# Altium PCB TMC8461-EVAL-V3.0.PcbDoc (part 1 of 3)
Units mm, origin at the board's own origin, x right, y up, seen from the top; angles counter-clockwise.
Board outline 79 x 85 mm, 4 copper layers (Top Layer, Mid1, Mid2, Bottom Layer), stack 1.572 mm thick; 182 components, 192 nets, 883 pads, 381 vias.
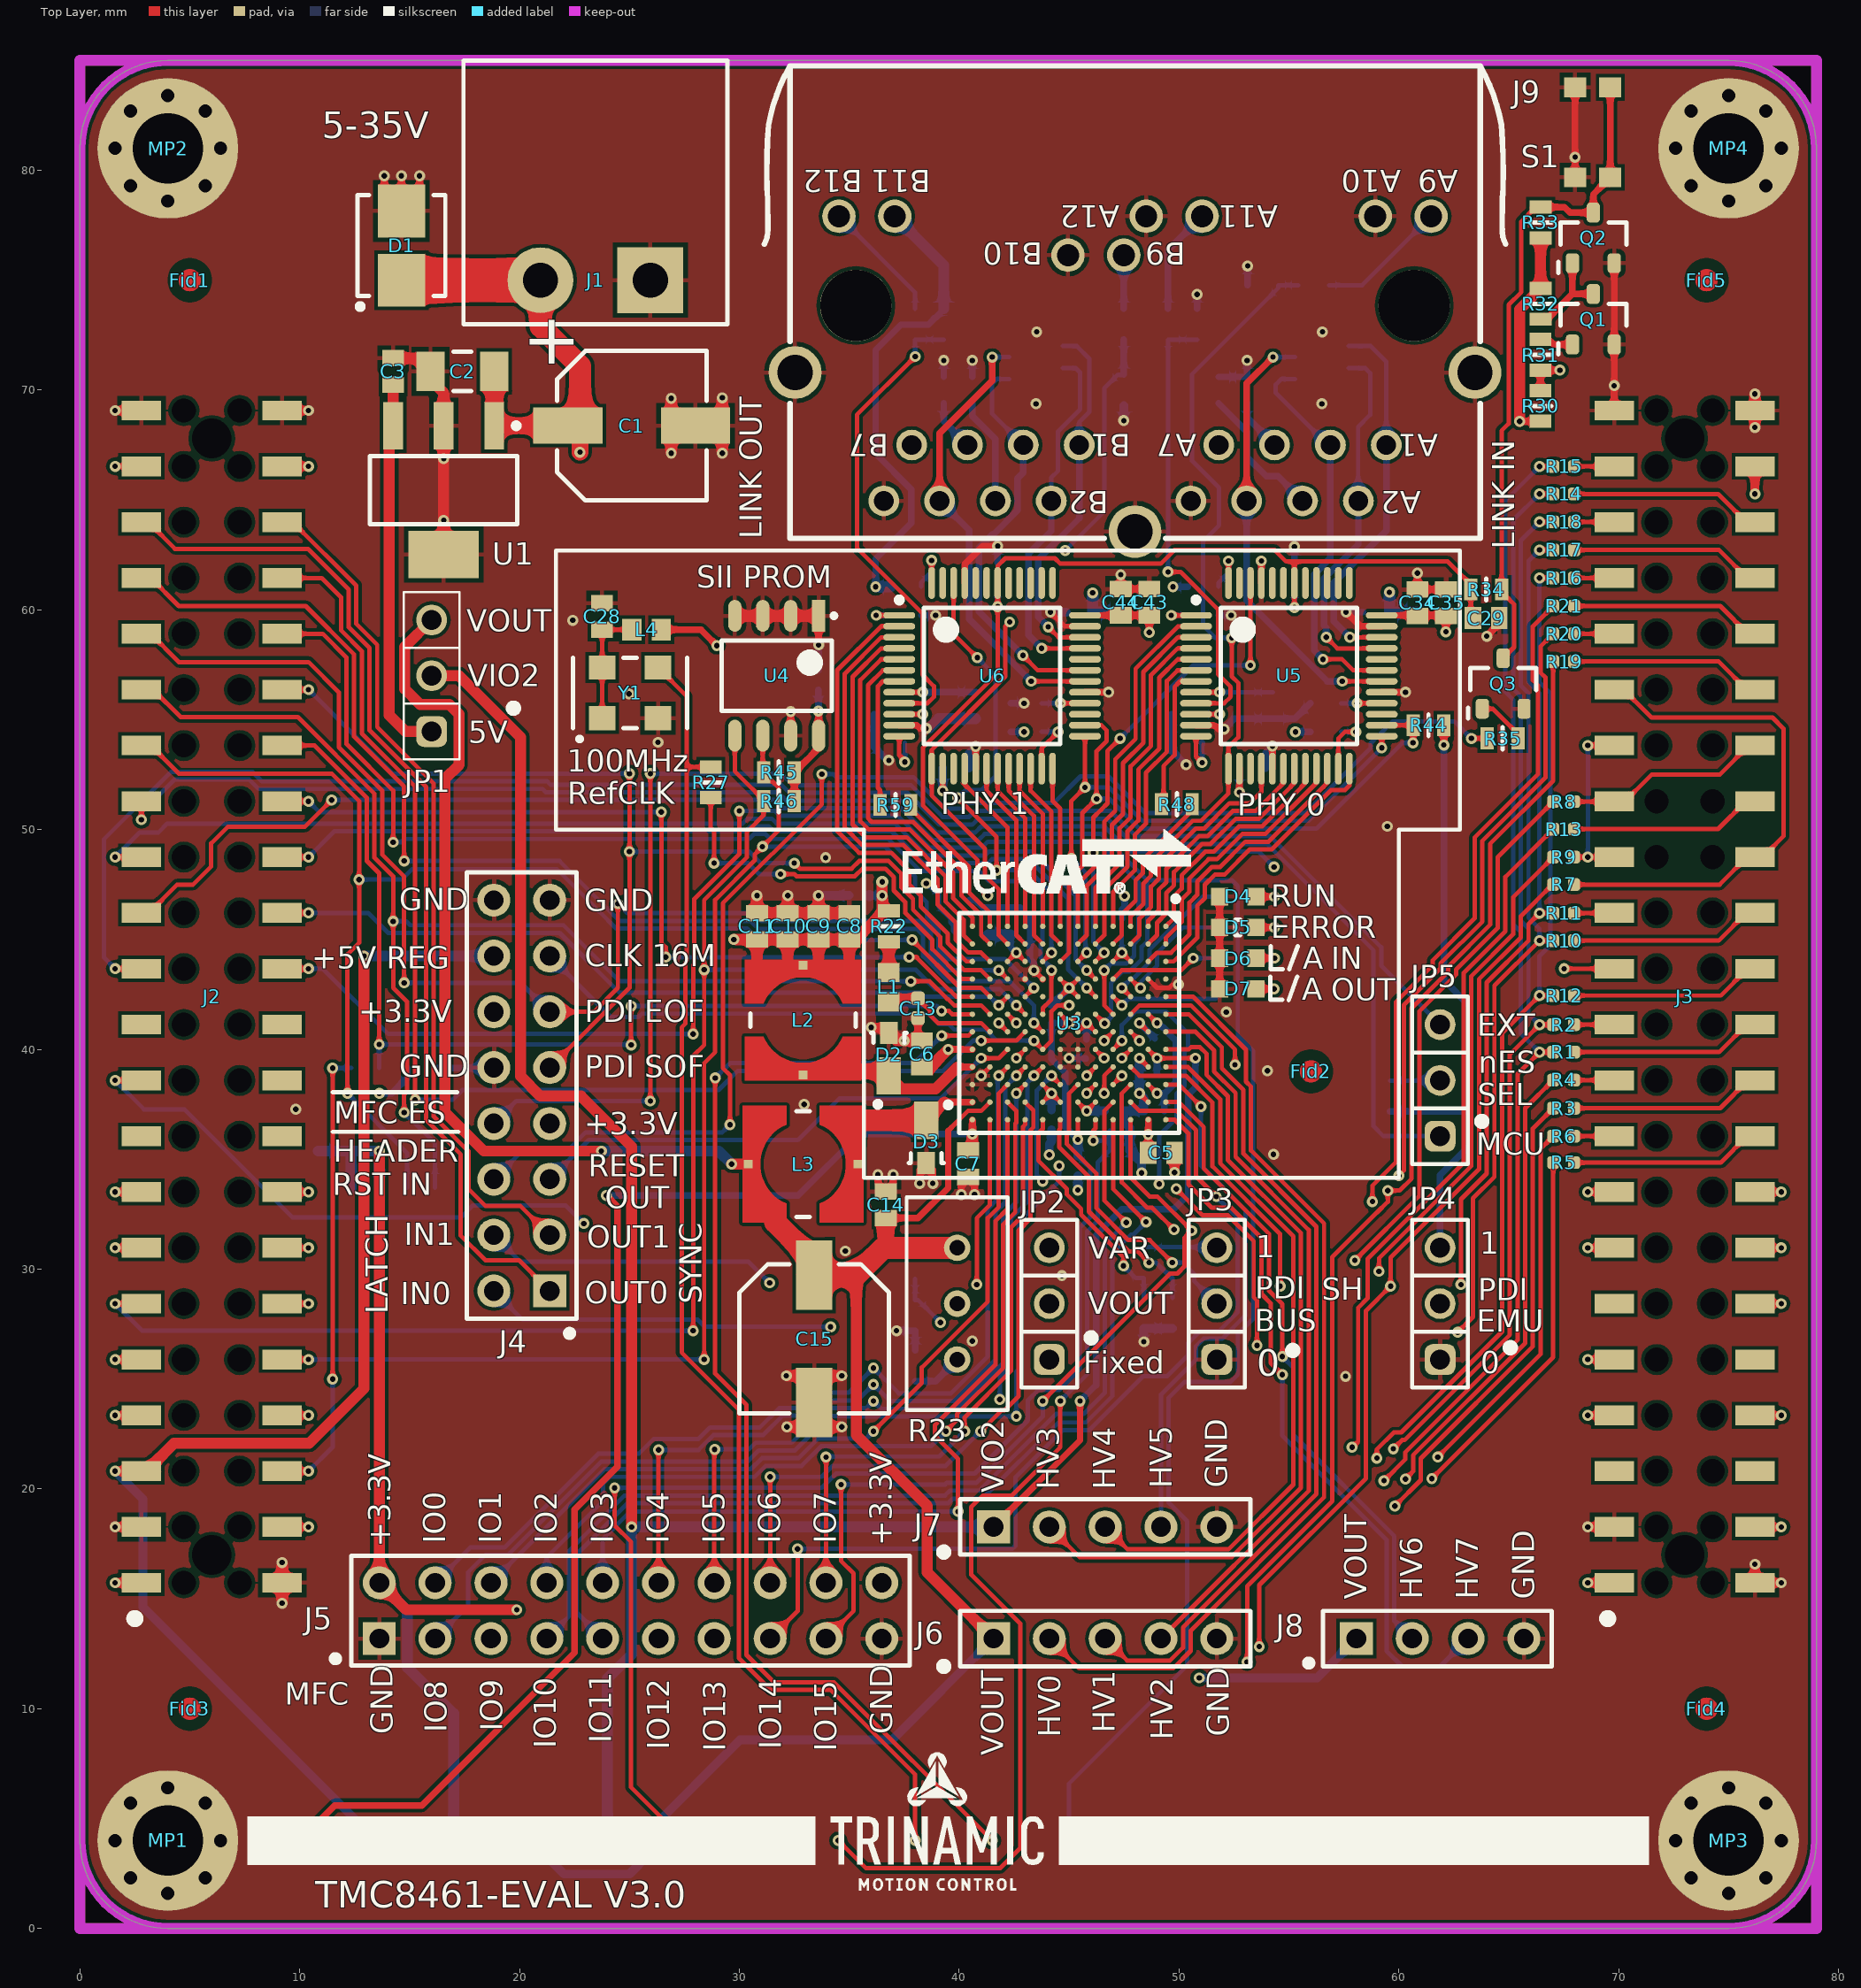
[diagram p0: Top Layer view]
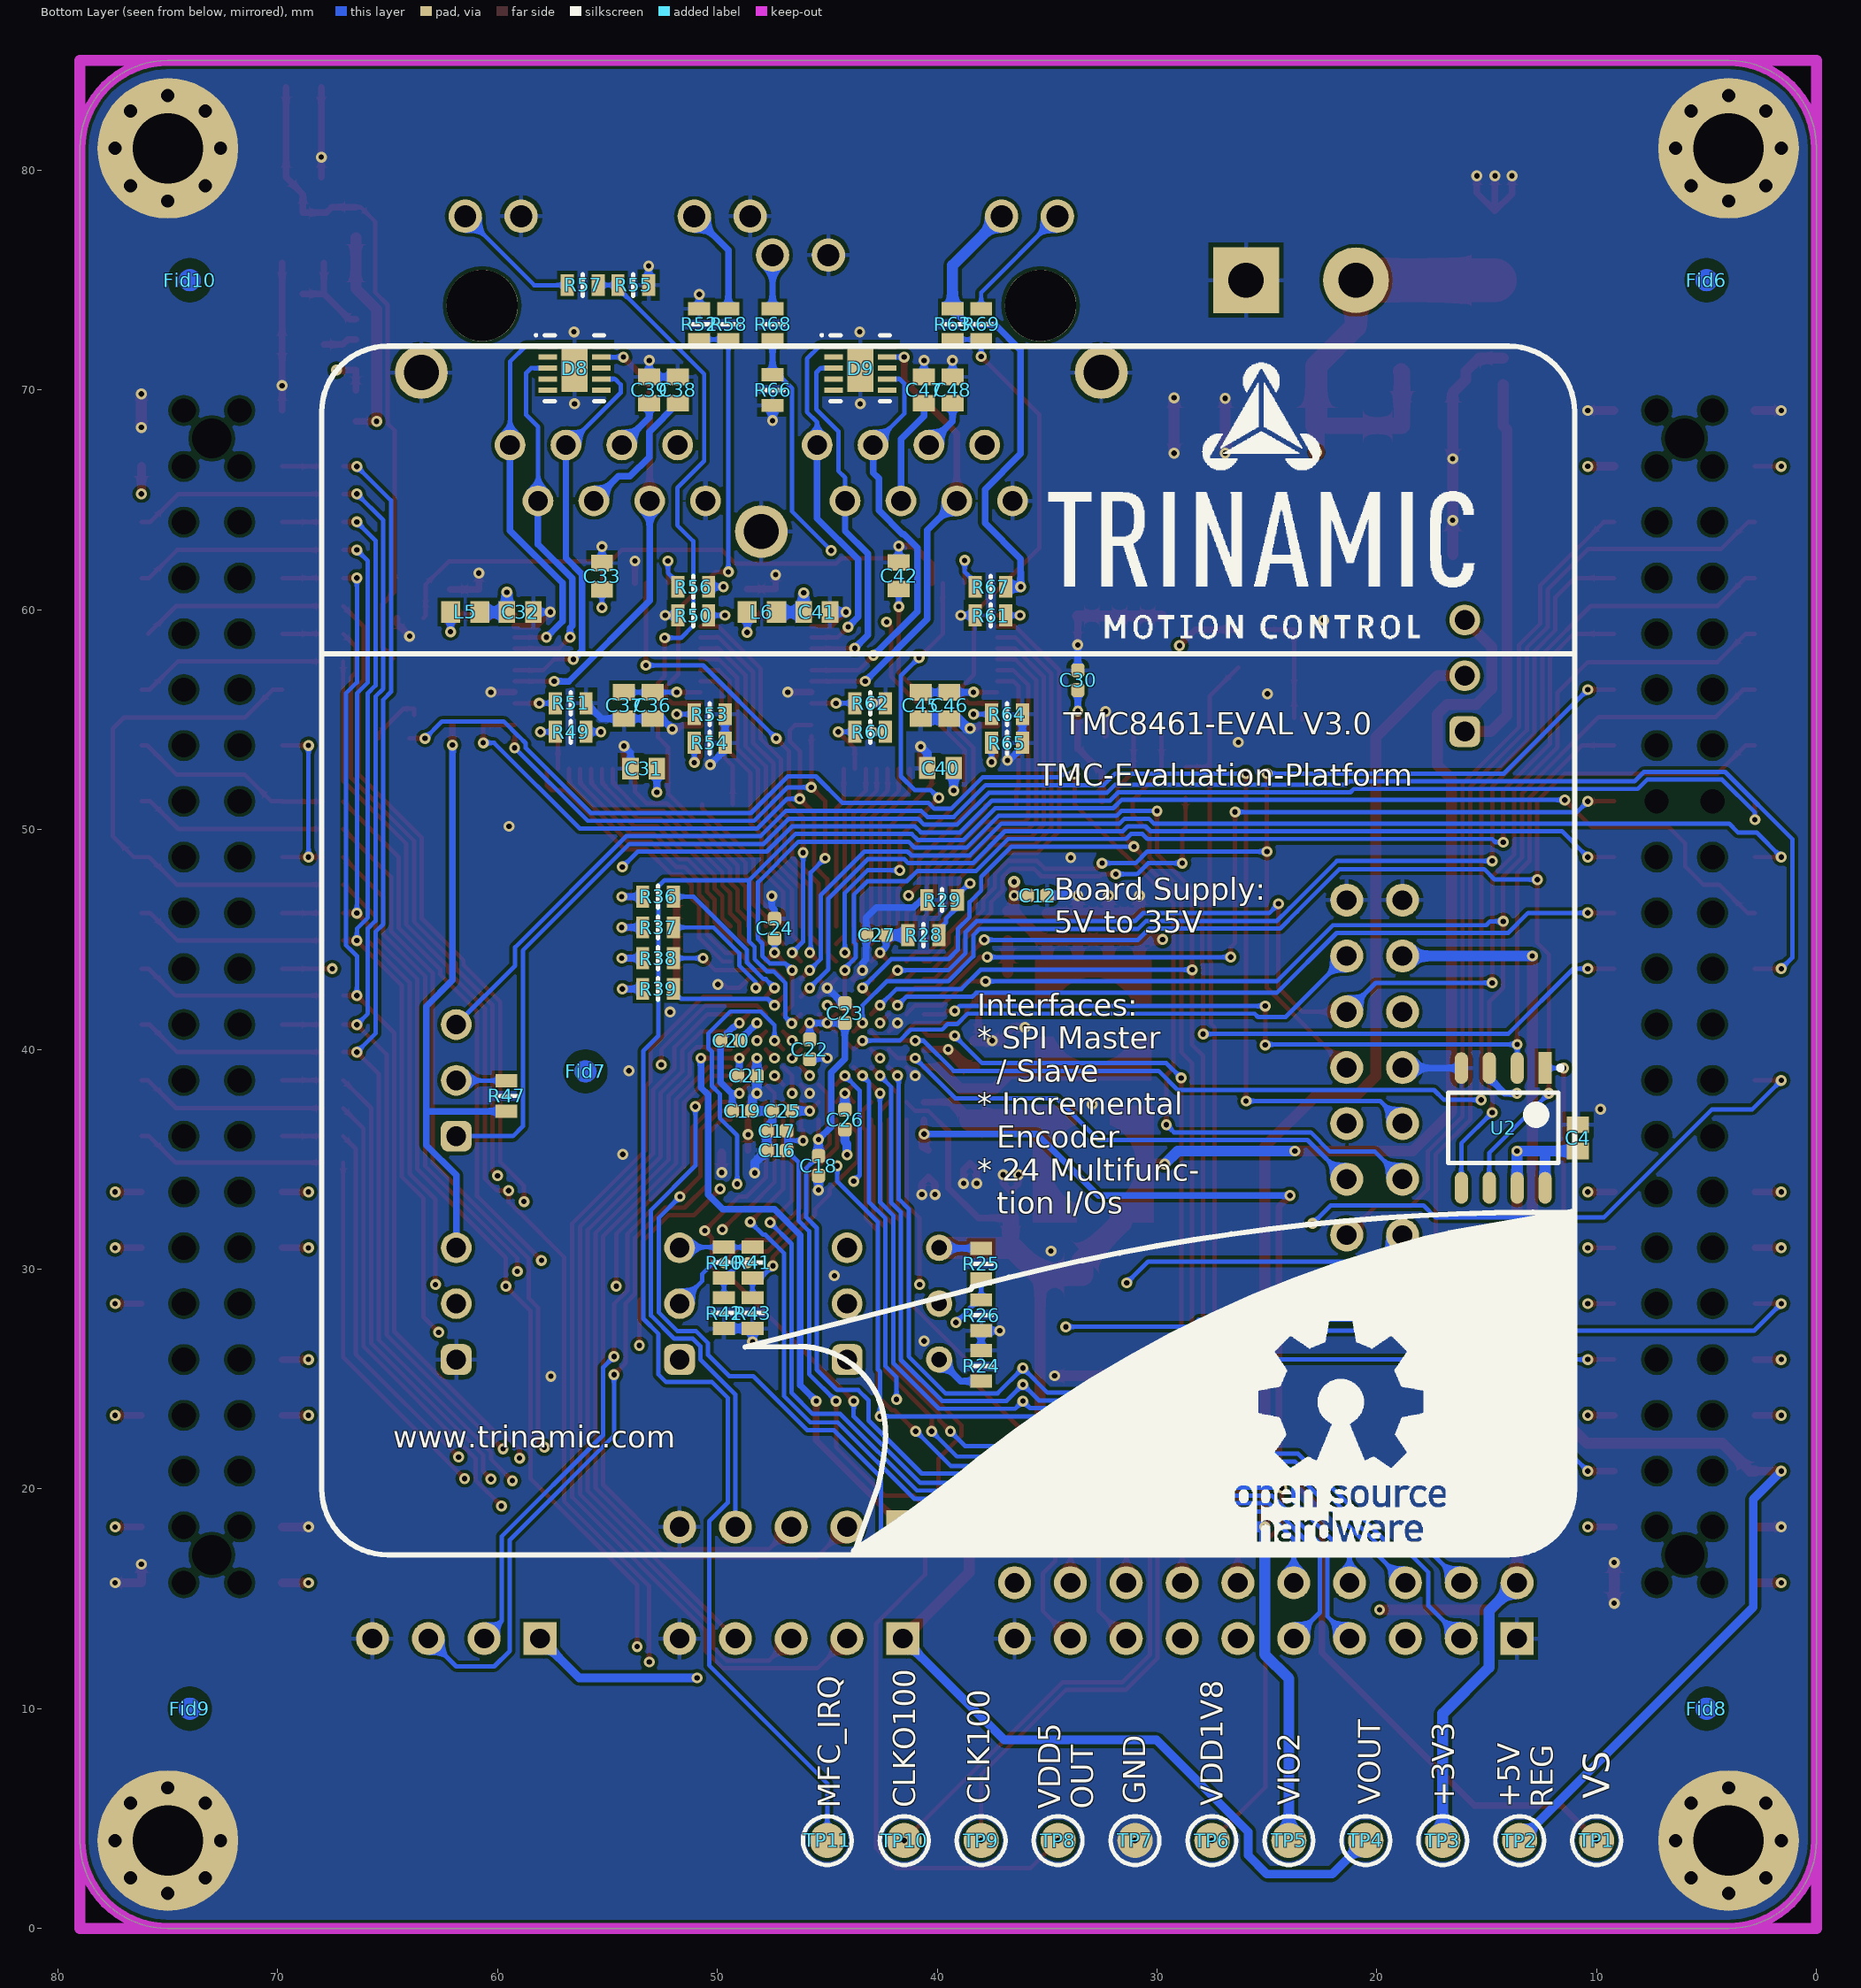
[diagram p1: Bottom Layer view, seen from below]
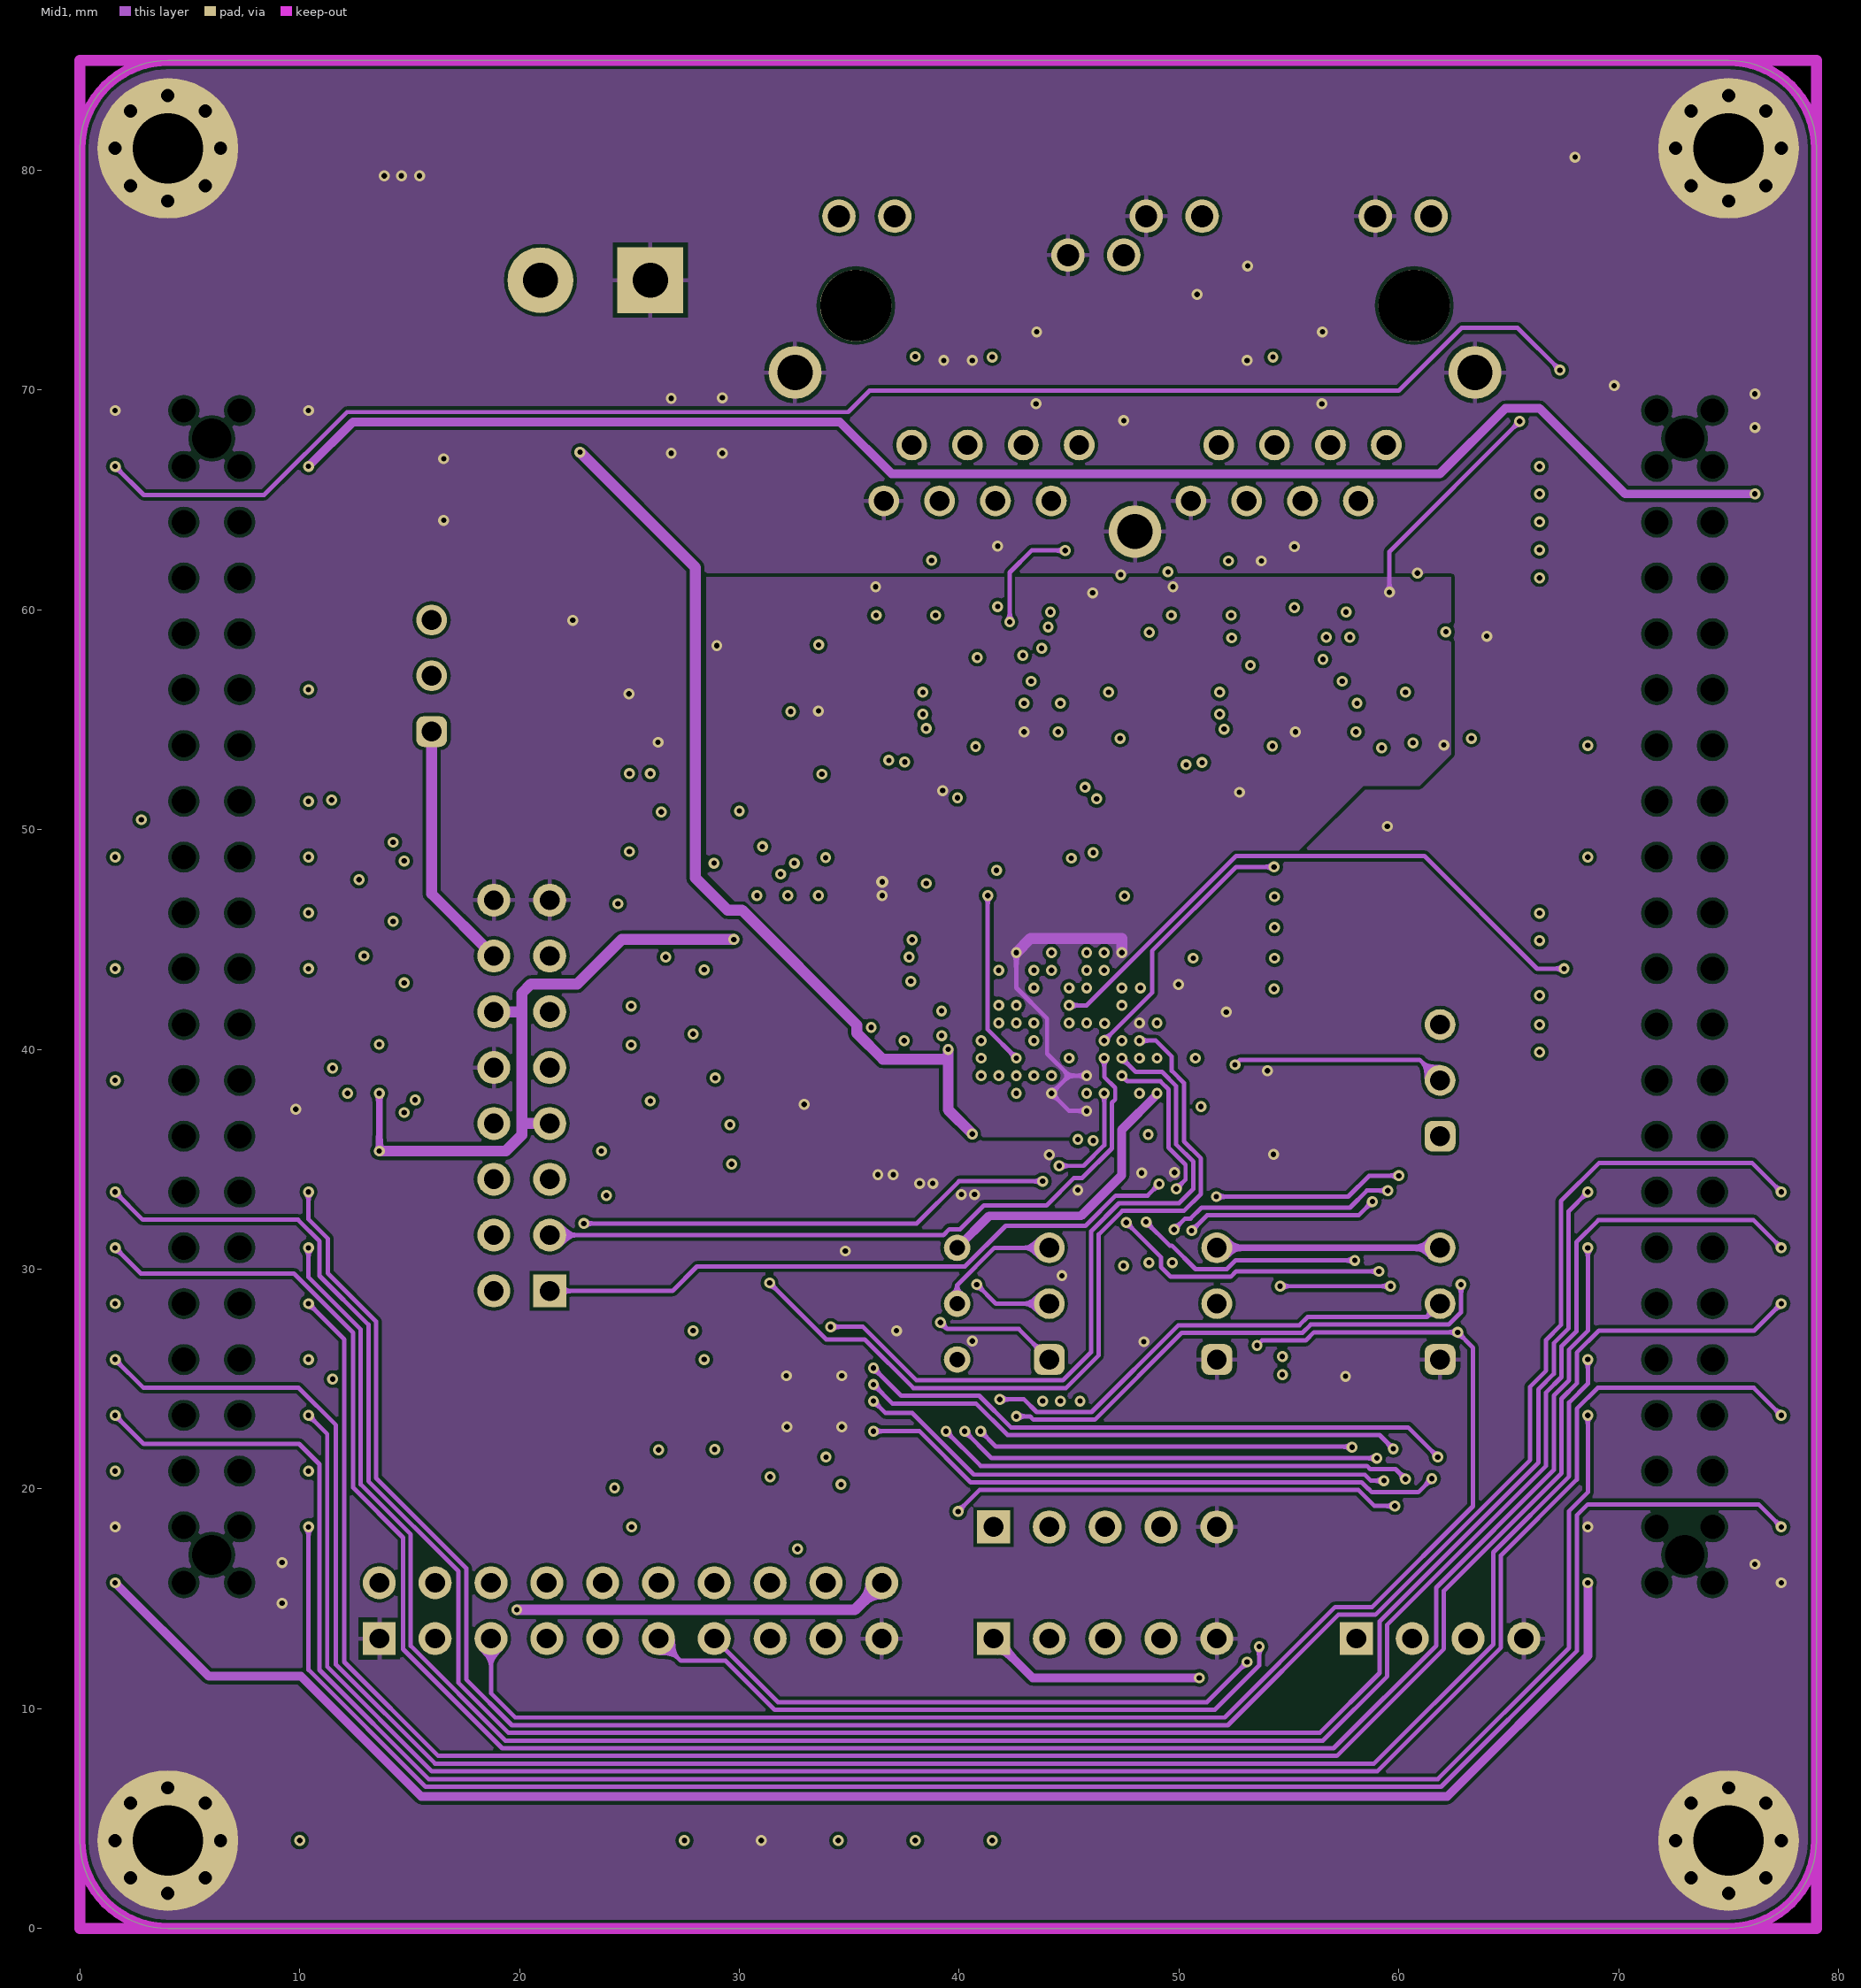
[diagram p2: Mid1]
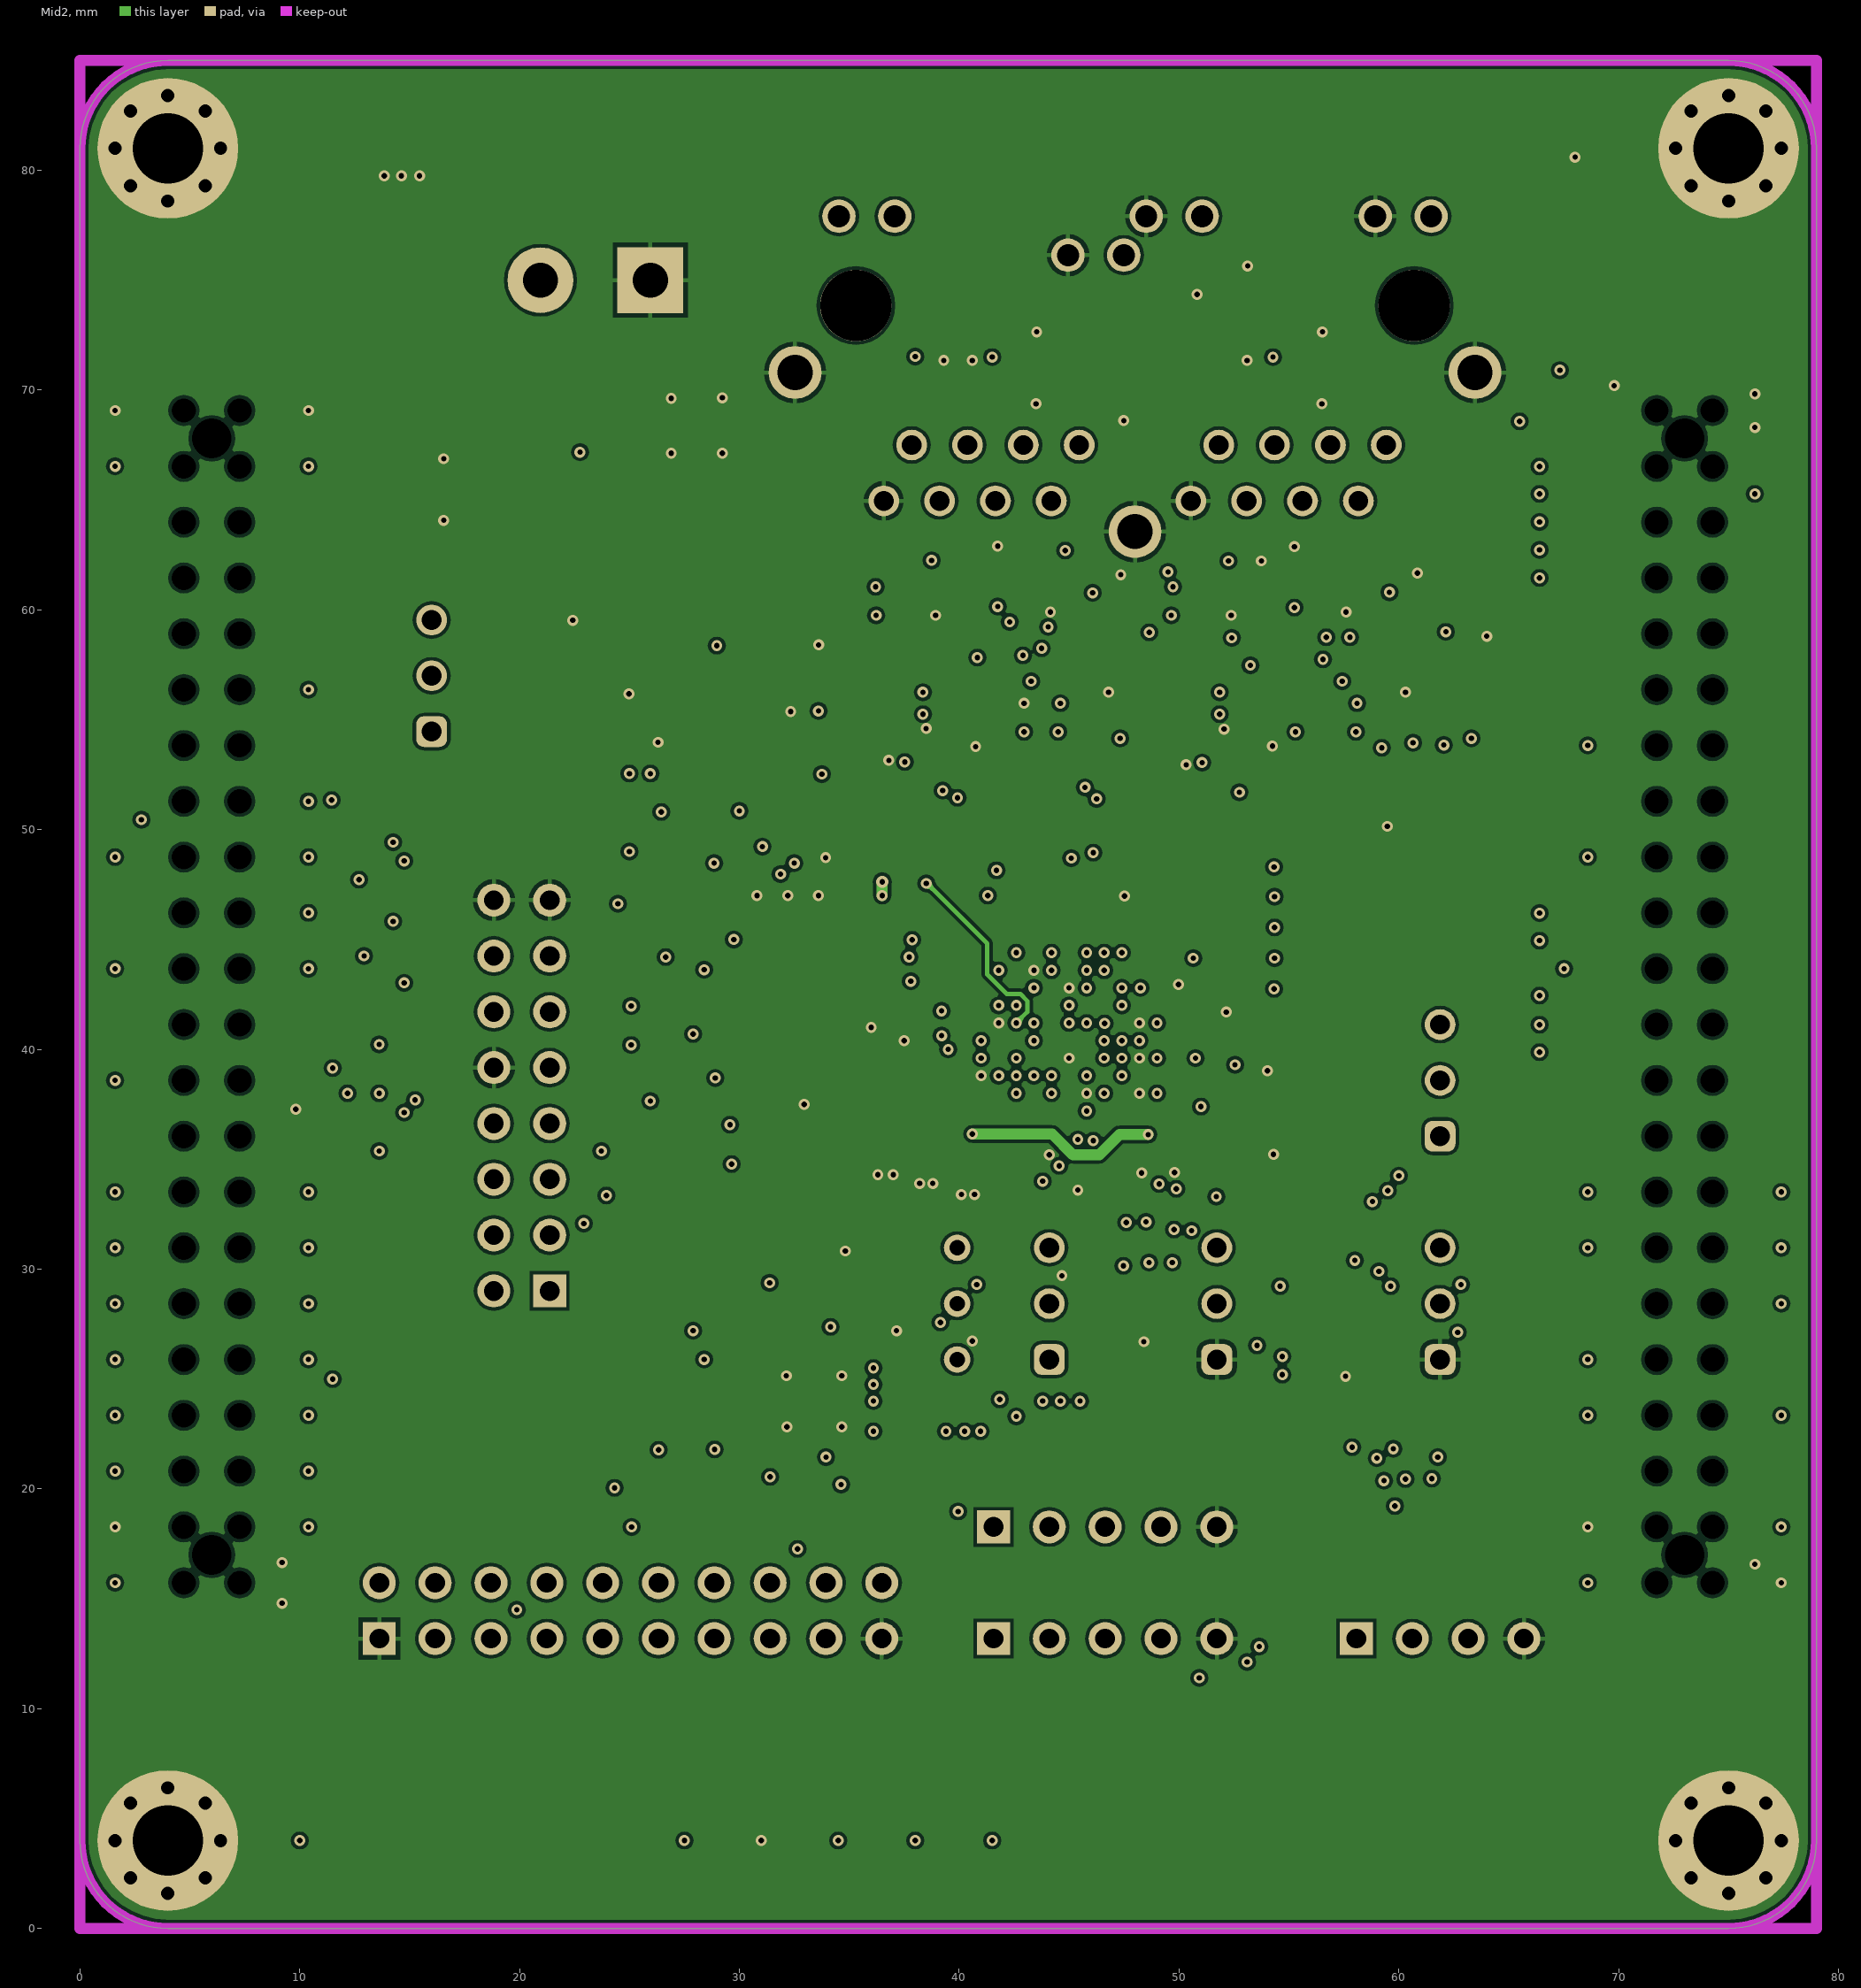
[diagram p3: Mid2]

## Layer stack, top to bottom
Top Soldermask: solder mask 0.0102, Solder Resist, Dk 3.5
Top Layer: signal copper 0.035
Prepreg 7628-45: prepreg 0.36, Dk 4.6
Mid1: signal copper 0.036
High Tg 1,08mm 35??m/35??m: core 0.71, FR-4, Dk 4.6
Mid2: signal copper 0.036
Prepreg 7628-45: prepreg 0.36, Dk 4.6
Bottom Layer: signal copper 0.035
Bottom Soldermask: solder mask 0.0102, Solder Resist, Dk 3.5

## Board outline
0,4 0,81 cw(c4,81) 4,85 75,85 cw(c75,81) 79,81 79,4 cw(c75,4) 75,0 4,0 cw(c4,4)

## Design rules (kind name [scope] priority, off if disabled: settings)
Clearance [All] p1: gap=0.15 ignorepadtopadclearanceinfootprint=FALSE
ComponentClearance [All] p1: gap=0 collisioncheckmode=3 verticalgap=0 showdistances=TRUE
DiffPairsRouting [All] p1: maxlimit=0.25 minlimit=0.25 mostfreqgap=0.25 toplayer_minwidth=0.381 toplayer_maxwidth=0.381 toplayer_prefwidth=0.381 midlayer1_minwidth=0.381 midlayer1_maxwidth=0.381 midlayer1_prefwidth=0.381 midlayer2_minwidth=0.381 midlayer2_maxwidth=0.381 midlayer2_prefwidth=0.381 bottomlayer_minwidth=0.381 bottomlayer_maxwidth=0.381 bottomlayer_prefwidth=0.381 maxuncoupledlength=12.5
FabricationTestpoint [All] p1: side=3 testpointundercomponent=TRUE minsize=0.5 maxsize=2.54 preferedsize=1.524 minholesize=0 maxholesize=1.016 preferedholesize=0.813 testpointgrid=0.025 allowsidetop=TRUE allowsidebottom=TRUE usegrid=FALSE gridtolerance=0
Height [All] p1: minheight=0 maxheight=40 prefheight=12.5
HoleSize HoleSize-PTH [All] p1: absolutevalues=TRUE maxlimit=6 minlimit=0.2 maxpercent=80.000 minpercent=20.000
HoleToHoleClearance [All] p1: gap=0.15 allowstackedmicrovias=TRUE
MinimumAnnularRing "Minimum IAR  >0.45mm" [((ObjectKind = 'Pad') OR (ObjectKind = 'Via')) And (Layer = 'MultiLayer') And (HoleDiameter > AsMM(0.45))] p1: minimumring=0.15 // minimum inner annular ring for pads > 0.45mm finished hole size
MinimumAnnularRing "Minimum IAR <=0.45mm" [((ObjectKind = 'Pad') OR (ObjectKind = 'Via')) And (Layer = 'MultiLayer') And (HoleDiameter <= AsMM(0.45))] p2: minimumring=0.124 // minimum inner annular ring for pads <= 0.45mm finished hole size
MinimumSolderMaskSliver [All] p1: minsoldermaskwidth=0.1
PlaneClearance PlaneClearance-IPI [All] p1: clearance=0.4
PlaneConnect [All] p1: planeconnectstyle=Relief reliefexpansion=0.4 reliefentries=4 reliefconductorwidth=0.2 reliefairgap=0.2
PolygonConnect PolygonConnect-Shunt [HasFootprint('RESC5025X07N')] p1: connectstyle=Direct reliefconductorwidth=0.254 reliefentries=4 polygonreliefangle="90 Angle" airgapwidth=0.254
PolygonConnect PolygonConnect-MT [HasFootprint('MTG3,2_6,4-VIA')] p2: connectstyle=Direct reliefconductorwidth=0.254 reliefentries=4 polygonreliefangle="90 Angle" airgapwidth=0.254
PolygonConnect PolygonConnect-JP2 [HasFootprint('691313710002')] p3: connectstyle=Relief reliefconductorwidth=0.7 reliefentries=4 polygonreliefangle="90 Angle" airgapwidth=0.4
PolygonConnect PolygonConnect-CAP [HasFootprint('CAPAE12_5X40')] p4: connectstyle=Relief reliefconductorwidth=0.7 reliefentries=4 polygonreliefangle="90 Angle" airgapwidth=0.4
PolygonConnect PolygonConnect-TP [HasFootprint('TP100P254')] p5: connectstyle=Direct reliefconductorwidth=0.254 reliefentries=4 polygonreliefangle="90 Angle" airgapwidth=0.254
PolygonConnect PolygonConnect-TP_1 [HasFootprint('TP100P254-TH')] p6: connectstyle=Relief reliefconductorwidth=0.5 reliefentries=4 polygonreliefangle="90 Angle" airgapwidth=0.4
PolygonConnect PolygonConnect-MOSFET [HasFootprint('PG-TDSON-8')] p7: connectstyle=Direct reliefconductorwidth=0.254 reliefentries=4 polygonreliefangle="90 Angle" airgapwidth=0.254
PolygonConnect PolygonConnect-CAPC3225N [HasFootprint('CAPC3225N')] p8: connectstyle=Direct reliefconductorwidth=0.254 reliefentries=4 polygonreliefangle="90 Angle" airgapwidth=0.254
PolygonConnect PolygonConnect-Via [IsVia] p9: connectstyle=Direct reliefconductorwidth=0.2 reliefentries=4 polygonreliefangle="90 Angle" airgapwidth=0.254
PolygonConnect PolygonConnect-xTW [All] p10: connectstyle=Relief reliefconductorwidth=0.2 reliefentries=4 polygonreliefangle="90 Angle" airgapwidth=0.2
RoutingCorners [All] p1: cornerstyle=45-Degree minsetback=2.5 maxsetback=2.5
RoutingVias "RoutingVias <= 0.45mm" [All] p1: holewidth=0.25 width=0.6 viastyle="Through Hole" minholewidth=0.2 minwidth=0.5 maxholewidth=0.6 maxwidth=1
SilkToSilkClearance [All] p1: silktosilkclearance=0.2
SilkToSolderMaskClearance SilkscreenOverComponentPads [IsPad] p1: minsilkscreentomaskgap=0.2 clearancetoexposedcopper=TRUE
SolderMaskExpansion SolderMaskExpansionVia [IsVia] p1: expansion=0.1 soldermaskfromhole=TRUE
SolderMaskExpansion [All] p2: expansion=0.08
Width Width-xTW [All] p1: maxlimit=2 minlimit=0.15 preferedwidth=0.2 midlayer1_minwidth=0.2 midlayer2_minwidth=0.2 bottomlayer_minwidth=0.2 minimp=50.000000 maximp=50.000000 favimp=50.000000
18 further rules are at their usual default settings.

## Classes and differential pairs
component class TMC8461-EVAL-V3.0_Control: C28 C29 C30 D4 D5 D6 D7 J4 JP3 JP4 L4 Q1 Q2 Q3 R27 R28 R29 R30 R31 R32 R33 R34 R35 R36 R37 R38 R39 R40 R41 R42 R43 R44 R45 R46 S1 TP9 TP10 U4 Y1
component class TMC8461-EVAL-V3.0_Main: C1 C2 C3 C4 D1 J1 J2 J3 JP1 MP1 MP2 MP3 MP4 R1 R2 R3 R4 R5 R6 R7 R8 R9 R10 R11 R12 R13 R14 R15 R16 R17 R18 R19 R20 R21 TP1 TP2 TP3 TP4 TP5 TP6 TP7 U1 U2
component class TMC8461-EVAL-V3.0_MFC: J5 J6 J7 J8 JP5 R47 TP11
component class TMC8461-EVAL-V3.0_PHY_IN: C31 C32 C33 C34 C35 C36 C37 C38 C39 D8 J9 L5 R48 R49 R50 R51 R52 R53 R54 R55 R56 R57 R58 U5
component class TMC8461-EVAL-V3.0_PHY_OUT: C40 C41 C42 C43 C44 C45 C46 C47 C48 D9 L6 R59 R60 R61 R62 R63 R64 R65 R66 R67 R68 R69 U6
component class TMC8461-EVAL-V3.0_Power: C5 C6 C7 C8 C9 C10 C11 C12 C13 C14 C15 C16 C17 C18 C19 C20 C21 C22 C23 C24 C25 C26 C27 D2 D3 JP2 L1 L2 L3 R22 R23 R24 R25 R26 TP8 U3

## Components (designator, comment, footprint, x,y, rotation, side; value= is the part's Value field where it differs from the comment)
C1 "CAPP1" CAPAE7766X63N 25.105,68.38 r0 top value="47u, 35V"
C2 "CAPC" CAPC3216N 17.4,70.85 r0 top value=4.7u
C3 "CAPC" CAPC1608N 14.25,70.85 r270 top value=10u
C4 "CAPC" CAPC1608N 10.85,35.975 r270 bottom value=100n
C5 "CAPC" CAPC1608N 49.2,35.3 r180 top value=100n
C6 "CAPC" CAPC1608N 38.3,39.8 r270 top value=100n
C7 "CAPC" CAPC1608N 40.4,34.8 r90 top value=100n
C8 "CAPC" CAPC1608N 35,45.6 r270 top value=10u
C9 "CAPC" CAPC1608N 33.6,45.6 r270 top value=10u
C10 "CAPC" CAPC1608N 32.2,45.6 r270 top value=10u
C11 "CAPC" CAPC1608N 30.8,45.6 r270 top value=10u
C12 "CAPC" CAPC1005N 35.45,47.005 r0 bottom value=100n
C13 "CAPC" CAPC1005N 38.125,41.875 r90 top value=100n
C14 "CAPC" CAPC1608N 36.658,32.926 r270 top value=100n
C15 "CAPP1" CAPAE7766X63N 33.407,26.83 r270 top value="47u, 35V"
C16 "CAPC" CAPC1005N 47.3,35.4 r180 bottom value=100n
C17 "CAPC" CAPC1005N 47.3,36.3 r180 bottom value=100n
C18 "CAPC" CAPC1005N 45.4,34.7 r90 bottom value=100n
C19 "CAPC" CAPC1005N 48.875,37.2 r0 bottom value=100n
C20 "CAPC" CAPC1005N 49.4,40.4 r0 bottom value=100n
C21 "CAPC" CAPC1005N 48.65,38.8 r0 bottom value=100n
C22 "CAPC" CAPC1005N 45.8,40 r90 bottom value=100n
C23 "CAPC" CAPC1005N 44.2,41.65 r270 bottom value=100n
C24 "CAPC" CAPC1005N 47.4,45.5 r270 bottom value=100n
C25 "CAPC" CAPC1005N 47.05,37.2 r180 bottom value=100n
C26 "CAPC" CAPC1005N 44.2,36.8 r90 bottom value=100n
C27 "CAPC" CAPC1005N 42.775,45.2 r180 bottom value=100n
C28 "CAPC" CAPC1608N 23.75,59.7 r270 top value=100n
C29 "CAPC" CAPC1608N 63.975,59.625 r180 top value=10n
C30 "CAPC" CAPC1005N 33.6,56.8 r270 bottom value=100n
C31 "CAPC" CAPC1608N 53.35,52.775 r180 bottom value=100n
C32 "CAPC" CAPC1608N 58.975,59.9 r0 bottom value=100n
C33 "CAPC" CAPC1608N 55.25,61.525 r270 bottom value=10n
C34 "CAPC" CAPC1608N 60.85,60.325 r270 top value=10u
C35 "CAPC" CAPC1608N 62.15,60.325 r270 top value=100n
C36 "CAPC" CAPC1608N 52.95,55.65 r90 bottom value=10u
C37 "CAPC" CAPC1608N 54.25,55.65 r90 bottom value=100n
C38 "CAPC" CAPC1608N 51.8,70 r270 bottom value=10n
C39 "CAPC" CAPC1608N 53.1,70 r270 bottom value=10n
C40 "CAPC" CAPC1608N 39.85,52.8 r180 bottom value=100n
C41 "CAPC" CAPC1608N 45.475,59.9 r0 bottom value=100n
C42 "CAPC" CAPC1608N 41.75,61.55 r270 bottom value=10n
C43 "CAPC" CAPC1608N 48.65,60.35 r270 top value=10u
C44 "CAPC" CAPC1608N 47.35,60.35 r270 top value=100n
C45 "CAPC" CAPC1608N 40.75,55.65 r90 bottom value=10u
C46 "CAPC" CAPC1608N 39.45,55.65 r90 bottom value=100n
C47 "CAPC" CAPC1608N 40.6,70 r270 bottom value=10n
C48 "CAPC" CAPC1608N 39.3,70 r270 bottom value=10n
D1 "TVS" DIOM4336X25N 14.625,76.575 r90 top value=33V,600W
D2 "DIO-SCHOTTKY" SODFL250130X73N 36.8,39.6 r90 top value="1A, 60V"
D3 "DIO-SCHOTTKY" SODFL250130X73N 38.5,35.975 r270 top value="1A, 60V"
D4 "DIO-LED" LED-KPT1608G-MFG 52.675,46.95 r0 top value="SB Green"
D5 "DIO-LED" LED-KPT1608R-MFG 52.675,45.55 r0 top value="HE Red"
D6 "DIO-LED" LED-KPT1608G-MFG 52.675,44.15 r0 top value="SB Green"
D7 "DIO-LED" LED-KPT1608G-MFG 52.675,42.75 r0 top value="SB Green"
D8 "SP3304N" SON50P260X55_HS-11N-LF 56.5,71 r180 bottom value=4xETH,300W
D9 "SP3304N" SON50P260X55_HS-11N-LF 43.5,71 r180 bottom value=4xETH,300W
Fid1 "Comment" FID10X20 5,75 r90 top
Fid2 "Comment" FID10X20 56,39 r90 top
Fid3 "Comment" FID10X20 5,10 r90 top
Fid4 "Comment" FID10X20 74,10 r90 top
Fid5 "Comment" FID10X20 74,75 r90 top
Fid6 "Comment" FID10X20 5,75 r90 bottom
Fid7 "Comment" FID10X20 56,39 r90 bottom
Fid8 "Comment" FID10X20 5,10 r90 bottom
Fid9 "Comment" FID10X20 74,10 r90 bottom
Fid10 "Comment" FID10X20 74,75 r90 bottom
J1 "HDR1x2A" AKL320-02 23.45,75 r0 top value="2 pin"
J2 "PTC" HLE-122-02-F-DV 6,42.4 r90 top value=44pin
J3 "PTC" HLE-122-02-F-DV 73,42.4 r90 top value=44pin
J4 "HDR2x8" SAMTEC_TSW-108-07-G-D 20.1,37.9 r90 top value=2x8
J5 "HDR2x10" SAMTEC_TSW-110-07-G-D 25.05,14.46 r0 top value=2x10
J6 "HDR1x5" SAMTEC_TSW-105-07-G-S 46.64,13.19 r0 top value=1x5
J7 "HDR1x5" SAMTEC_TSW-105-07-G-S 46.64,18.27 r0 top value=1x5
J8 "HDR1x4" SAMTEC_TSW-104-07-G-S 61.88,13.19 r0 top value=1x5
J9 "RJMAGX2" WUERTH_7499021125 48,74 r180 top value=2xRJ45MAG
JP1 "JUMPER1X3A" SAMTEC_TSW-103-07-G-S 16,57 r180 top
JP2 "JUMPER1X3A" SAMTEC_TSW-103-07-G-S 44.1,28.43 r180 top
JP3 "JUMPER1X3A" SAMTEC_TSW-103-07-G-S 51.72,28.43 r180 top
JP4 "JUMPER1X3A" SAMTEC_TSW-103-07-G-S 61.88,28.43 r180 top
JP5 "JUMPER1X3A" SAMTEC_TSW-103-07-G-S 61.88,38.59 r180 top
L1 "FB" INDC1608X09N 36.8,42.825 r270 top value=600
L2 "INDM" WE-744042680 32.899,41.333 r90 top value=68u
L3 "INDM" WE-744042680 32.899,34.78 r180 top value=68u
L4 "FB" INDC1608X09N 25.775,59.1 r0 top value=600
L5 "FB" INDC1608X09N 61.475,59.9 r0 bottom value=600
L6 "FB" INDC1608X09N 47.975,59.9 r0 bottom value=600
MP1 "MTG" MTG3,2_6,4-VIA 4,4 r0 top value="3.2x6.4 VIA"
MP2 "MTG" MTG3,2_6,4-VIA 4,81 r0 top value="3.2x6.4 VIA"
MP3 "MTG" MTG3,2_6,4-VIA 75,4 r0 top value="3.2x6.4 VIA"
MP4 "MTG" MTG3,2_6,4-VIA 75,81 r0 top value="3.2x6.4 VIA"
Q1 "BJT-NPN1" SOT95P280X130-3N 68.85,73.225 r90 top value="30V 100mA"
Q2 "BJT-NPN1" SOT95P280X130-3N 68.85,76.925 r90 top value="30V 100mA"
Q3 "BJT-NPN1" SOT95P280X130-3N 64.75,56.65 r90 top value="30V 100mA"
R1 "RESC" RESC1005N 67.5,39.875 r0 top value=0
R2 "RESC" RESC1005N 67.5,41.125 r0 top value=0
R3 "RESC" RESC1005N 67.5,37.325 r0 top value=0
R4 "RESC" RESC1005N 67.5,38.6 r0 top value=0
R5 "RESC" RESC1005N 67.5,34.85 r0 top value=0
R6 "RESC" RESC1005N 67.5,36.05 r0 top value=0
R7 "RESC" RESC1005N 67.5,47.5 r0 top value=0
R8 "RESC" RESC1005N 67.5,51.275 r0 top value=0
R9 "RESC" RESC1005N 67.5,48.75 r0 top value=0
R10 "RESC" RESC1005N 67.5,44.95 r0 top value=0
R11 "RESC" RESC1005N 67.5,46.2 r0 top value=0
R12 "RESC" RESC1005N 67.5,42.45 r0 top value=0
R13 "RESC" RESC1005N 67.5,50.025 r0 top value=0
R14 "RESC" RESC1005N 67.5,65.275 r0 top value=0
R15 "RESC" RESC1005N 67.5,66.525 r0 top value=0
R16 "RESC" RESC1005N 67.5,61.45 r0 top value=0
R17 "RESC" RESC1005N 67.5,62.725 r0 top value=0
R18 "RESC" RESC1005N 67.5,64 r0 top value=0
R19 "RESC" RESC1005N 67.5,57.65 r0 top value=0
R20 "RESC" RESC1005N 67.5,58.91 r0 top value=0
R21 "RESC" RESC1005N 67.5,60.175 r0 top value=0
R22 "RESC" RESC1608N 36.8,45.6 r270 top value=1
R23 "VRES" VISHAY_T93YA 39.909,28.43 r180 top value=100k
R24 "RESC" RESC1608N 38,25.6 r270 bottom value=4.7k
R25 "RESC" RESC1608N 38,30.25 r90 bottom value=47k5
R26 "RESC" RESC1608N 38,27.9 r90 bottom value=15k
R27 "RESC" RESC1608N 28.7,52.15 r270 top value=33
R28 "RESC" RESC1608N 40.625,45.2 r0 bottom value=10k
R29 "RESC" RESC1608N 39.775,46.8 r180 bottom value=DNP
R30 "RESC" RESC1608N 66.445,69.28 r90 top value=10k
R31 "RESC" RESC1608N 66.445,71.605 r270 top value=10k
R32 "RESC" RESC1608N 66.45,73.925 r90 top value=10k
R33 "RESC" RESC1608N 66.45,77.625 r270 top value=10k
R34 "RESC" RESC1608N 63.975,60.925 r180 top value=22
R35 "RESC" RESC1608N 64.725,54.15 r180 top value=10k
R36 "RESC" RESC1608N 52.7,46.95 r0 bottom value=1k
R37 "RESC" RESC1608N 52.7,45.55 r0 bottom value=1k
R38 "RESC" RESC1608N 52.7,44.15 r0 bottom value=1k
R39 "RESC" RESC1608N 52.7,42.75 r0 bottom value=1k
R40 "RESC" RESC1608N 49.7,30.3 r90 bottom value=DNP
R41 "RESC" RESC1608N 48.4,30.3 r90 bottom value=DNP
R42 "RESC" RESC1608N 49.7,28 r90 bottom value=0
R43 "RESC" RESC1608N 48.4,28 r90 bottom value=0
R44 "RESC" RESC1608N 61.35,54.75 r0 top value=4.7k
R45 "RESC" RESC1608N 31.8,52.6 r0 top value=2k
R46 "RESC" RESC1608N 31.8,51.3 r0 top value=2k
R47 "RESC" RESC1608N 59.6,37.88 r270 bottom value=10k
R48 "RESC" RESC1608N 49.9,51.15 r180 top value=22
R49 "RESC" RESC1608N 56.675,54.45 r0 bottom value=4.7k
R50 "RESC" RESC1608N 51.1,59.75 r180 bottom value=4.7k
R51 "RESC" RESC1608N 56.675,55.75 r0 bottom value=6.19k
R52 "RESC" RESC1608N 50.825,73 r270 bottom value=5.1k
R53 "RESC" RESC1608N 50.35,55.25 r0 bottom value=5.1k
R54 "RESC" RESC1608N 50.35,53.95 r0 bottom value=5.1k
R55 "RESC" RESC1608N 53.825,74.775 r0 bottom value=5.1k
R56 "RESC" RESC1608N 51.1,61.05 r180 bottom value=4.7k
R57 "RESC" RESC1608N 56.125,74.775 r0 bottom value=510
R58 "RESC" RESC1608N 49.5,73 r90 bottom value=510
R59 "RESC" RESC1608N 37.1,51.125 r180 top value=22
R60 "RESC" RESC1608N 43.05,54.45 r0 bottom value=4.7k
R61 "RESC" RESC1608N 37.575,59.75 r180 bottom value=4.7k
R62 "RESC" RESC1608N 43.05,55.75 r0 bottom value=6.19k
R63 "RESC" RESC1608N 39.3,73 r90 bottom value=5.1k
R64 "RESC" RESC1608N 36.825,55.25 r0 bottom value=5.1k
R65 "RESC" RESC1608N 36.825,53.95 r0 bottom value=5.1k
R66 "RESC" RESC1608N 47.49,70 r90 bottom value=5.1k
R67 "RESC" RESC1608N 37.575,61.05 r180 bottom value=4.7k
R68 "RESC" RESC1608N 47.49,73 r90 bottom value=510
R69 "RESC" RESC1608N 38,73 r90 bottom value=510
S1 "SW_4PIN" CK-KMR2 68.82,81.73 r270 top
TP1 "VS" TP100P254 10,4 r90 bottom value="c160 (P100 probe)"
TP2 "+5V_REG" TP100P254 13.5,4 r90 bottom value="c160 (P100 probe)"
TP3 "+3V3" TP100P254 17,4 r90 bottom value="c160 (P100 probe)"
TP4 "VOUT" TP100P254 20.5,4 r90 bottom value="c160 (P100 probe)"
TP5 "VIO2" TP100P254 24,4 r270 bottom value="c160 (P100 probe)"
TP6 "VDD1V8" TP100P254 27.5,4 r0 bottom value="c160 (P100 probe)"
TP7 "GND" TP100P254 31,4 r0 bottom value="c160 (P100 probe)"
TP8 "VDD5_OUT" TP100P254 34.5,4 r0 bottom value="c160 (P100 probe)"
TP9 "CLK100" TP100P254 38,4 r0 bottom value="c160 (P100 probe)"
TP10 "CLKO100" TP100P254 41.5,4 r0 bottom value="c160 (P100 probe)"
TP11 "MFC_IRQ" TP100P254 45,4 r0 bottom value="c160 (P100 probe)"
U1 "LDO4-SOT223" SOT230P700X180-4N-TI 16.55,65.45 r270 top value="5V 1A"
U2 "" SOIC127P600X175-8N 14.25,36.425 r270 bottom value=128Kb
U3 "50588" BGA144C80P12X12_1000X1000X100 45,41.2 r270 top value=EthCat
U4 "24LC64" SOIC127P600X175-8N 31.7,57 r270 top value=64KB
U5 "IP101GA" TSQFP50P900X900X160-48N 55,57 r0 top
U6 "IP101GA" TSQFP50P900X900X160-48N 41.5,57 r0 top
Y1 "OSC-ASFLMB" OSC500X320X85N 25.03,56.225 r0 top value=100M

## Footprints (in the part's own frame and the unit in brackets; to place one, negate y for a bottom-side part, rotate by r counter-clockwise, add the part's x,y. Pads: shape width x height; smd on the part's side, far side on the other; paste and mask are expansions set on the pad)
AKL320-02 [mm] "Box header for AKL 349, 2-pin, RM 5.0"
  rect 3x3 hole 1.6: 1(2.5,0)
  round 3 hole 1.6: 2(-2.5,0)
  silkscreen extent -6,-2 6,10, body extent -6,-2 6,10, height 8.55
BGA144C80P12X12_1000X1000X100 [mm] "BGA, 144-Leads, Body 10.00x10.00mmx1.00mm, Pitch 0.80mm"
  round 0.25 smd: A1(-4.4,4.4) A2(-3.6,4.4) A3(-2.8,4.4) A4(-2,4.4) A5(-1.2,4.4) A6(-0.4,4.4) A7(0.4,4.4) A8(1.2,4.4) A9(2,4.4) A10(2.8,4.4) A11(3.6,4.4) A12(4.4,4.4) B1(-4.4,3.6) B2(-3.6,3.6) B3(-2.8,3.6) B4(-2,3.6) B5(-1.2,3.6) B6(-0.4,3.6) B7(0.4,3.6) B8(1.2,3.6) B9(2,3.6) B10(2.8,3.6) B11(3.6,3.6) B12(4.4,3.6) C1(-4.4,2.8) C2(-3.6,2.8) C3(-2.8,2.8) C4(-2,2.8) C5(-1.2,2.8) C6(-0.4,2.8) C7(0.4,2.8) C8(1.2,2.8) C9(2,2.8) C10(2.8,2.8) C11(3.6,2.8) C12(4.4,2.8) D1(-4.4,2) D2(-3.6,2) D3(-2.8,2) D4(-2,2) D5(-1.2,2) D6(-0.4,2) D7(0.4,2) D8(1.2,2) D9(2,2) D10(2.8,2) D11(3.6,2) D12(4.4,2) E1(-4.4,1.2) E2(-3.6,1.2) E3(-2.8,1.2) E4(-2,1.2) E5(-1.2,1.2) E6(-0.4,1.2) E7(0.4,1.2) E8(1.2,1.2) E9(2,1.2) E10(2.8,1.2) E11(3.6,1.2) E12(4.4,1.2) F1(-4.4,0.4) F2(-3.6,0.4) F3(-2.8,0.4) F4(-2,0.4) F5(-1.2,0.4) F6(-0.4,0.4) F7(0.4,0.4) F8(1.2,0.4) F9(2,0.4) F10(2.8,0.4) F11(3.6,0.4) F12(4.4,0.4) G1(-4.4,-0.4) G2(-3.6,-0.4) G3(-2.8,-0.4) G4(-2,-0.4) G5(-1.2,-0.4) G6(-0.4,-0.4) G7(0.4,-0.4) G8(1.2,-0.4) G9(2,-0.4) G10(2.8,-0.4) G11(3.6,-0.4) G12(4.4,-0.4) H1(-4.4,-1.2) H2(-3.6,-1.2) H3(-2.8,-1.2) H4(-2,-1.2) H5(-1.2,-1.2) H6(-0.4,-1.2) H7(0.4,-1.2) H8(1.2,-1.2) H9(2,-1.2) H10(2.8,-1.2) H11(3.6,-1.2) H12(4.4,-1.2) J1(-4.4,-2) J2(-3.6,-2) J3(-2.8,-2) J4(-2,-2) J5(-1.2,-2) J6(-0.4,-2) J7(0.4,-2) J8(1.2,-2) J9(2,-2) J10(2.8,-2) J11(3.6,-2) J12(4.4,-2) K1(-4.4,-2.8) K2(-3.6,-2.8) K3(-2.8,-2.8) K4(-2,-2.8) K5(-1.2,-2.8) K6(-0.4,-2.8) K7(0.4,-2.8) K8(1.2,-2.8) K9(2,-2.8) K10(2.8,-2.8) K11(3.6,-2.8) K12(4.4,-2.8) L1(-4.4,-3.6) L2(-3.6,-3.6) L3(-2.8,-3.6) L4(-2,-3.6) L5(-1.2,-3.6) L6(-0.4,-3.6) L7(0.4,-3.6) L8(1.2,-3.6) L9(2,-3.6) L10(2.8,-3.6) L11(3.6,-3.6) L12(4.4,-3.6) M1(-4.4,-4.4) M2(-3.6,-4.4) M3(-2.8,-4.4) M4(-2,-4.4) M5(-1.2,-4.4) M6(-0.4,-4.4) M7(0.4,-4.4) M8(1.2,-4.4) M9(2,-4.4) M10(2.8,-4.4) M11(3.6,-4.4) M12(4.4,-4.4)
  silkscreen extent -5.77,-5 5,5, body extent -5,-5 5,5, height 1
CAPAE7766X63N [mm] "Aluminum Electrolytic Capacitor, Body 6.60x6.60x6.30mm, IPC Medium Density"
  rect 3.15x1.65 smd: 1(-2.9,0) 2(2.9,0)
  silkscreen extent -3.4,-3.4 3.4,3.4, body extent -3.83,-3.4 3.83,3.4, height 6.3
CAPC1005N [mm] "Chip capacitor. C1005 (0402)."
  rrect49% 0.63x0.61 smd: 1(-0.45,0) 2(0.45,0)
  body extent -0.5,-0.25 0.5,0.25, height 0.55
CAPC1608N [mm] "Chip capacitor. C1608 (0603)."
  rect 0.75x1 smd: 1(-0.6,0) 2(0.6,0)
  body extent -0.8,-0.4 0.8,0.4, height 0.92
CAPC3216N [mm] "Chip capacitor. C3216 (1206)."
  rect 1.3x1.8 smd: 1(-1.45,0) 2(1.45,0)
  silkscreen extent -0.4,-0.9 0.4,0.9, body extent -1.6,-0.8 1.6,0.8, height 1.9
CK-KMR2 [mm] "Microminiature Tact Switch for SMT"
  rect 0.9x1 smd: 1(-2.05,0.8) 2(2.05,0.8) 3(-2.05,-0.8) 4(2.05,-0.8)
  body extent -2.3,-1.5 2.3,1.5, height 2.1
DIOM4336X25N [mm] "Molded Diode, 2-Leads, Body 4.32x3.63mm, IPC Medium Density, SMB, DO-214AA"
  rect 2.4x2.15 smd: 1(-1.575,0) 2(1.575,0)
  silkscreen extent -2.9,-2 2.3,2, body extent -2.52,-1.97 2.52,1.98, height 2.45
FID10X20 [mm] "Fiducial"
  Top Layer circle w0.5: c0,0 r0.25
  Top Layer region: 0,-0.5 -0.191,-0.462 -0.354,-0.354 -0.462,-0.191 -0.5,0 -0.5,0 -0.462,0.191 -0.354,0.354 -0.191,0.462 0,0.5 0,0.5 0.191,0.462 0.354,0.354 0.462,0.191 0.5,0 0.5,0 0.462,-0.191 0.354,-0.354 0.191,-0.462 0,-0.5
  Top Layer pour cut-out: 0,-1 -0.383,-0.924 -0.707,-0.707 -0.924,-0.383 -1,0 -1,0 -0.924,0.383 -0.707,0.707 -0.383,0.924 0,1 0,1 0.383,0.924 0.707,0.707 0.924,0.383 1,0 1,0 0.924,-0.383 0.707,-0.707 0.383,-0.924 0,-1
HLE-122-02-F-DV [mm] "24 Position Receptacle, Bottom Entry Connector Gold 0.100\" (2.54mm) Surface Mount"
  round 1 hole 1.1 unplated: 0(-26.67,-1.27) 0(-26.67,1.27) 0(-24.13,-1.27) 0(-24.13,1.27) 0(-21.59,-1.27) 0(-21.59,1.27) 0(-19.05,-1.27) 0(-19.05,1.27) 0(-16.51,-1.27) 0(-16.51,1.27) 0(-13.97,-1.27) 0(-13.97,1.27) 0(-11.43,-1.27) 0(-11.43,1.27) 0(-8.89,-1.27) 0(-8.89,1.27) 0(-6.35,-1.27) 0(-6.35,1.27) 0(-3.81,-1.27) 0(-3.81,1.27) 0(-1.27,-1.27) 0(-1.27,1.27) 0(1.27,-1.27) 0(1.27,1.27) 0(3.81,-1.27) 0(3.81,1.27) 0(6.35,-1.27) 0(6.35,1.27) 0(8.89,-1.27) 0(8.89,1.27) 0(11.43,-1.27) 0(11.43,1.27) 0(13.97,-1.27) 0(13.97,1.27) 0(16.51,-1.27) 0(16.51,1.27) 0(19.05,-1.27) 0(19.05,1.27) 0(21.59,-1.27) 0(21.59,1.27) 0(24.13,-1.27) 0(24.13,1.27) 0(26.67,-1.27) 0(26.67,1.27)
  round 1 hole 1.8 unplated: 0(-25.4,0) 0(25.4,0)
  rect 0.9x1.8 smd: 1(-26.67,3.2) 2(-26.67,-3.2) 3(-24.13,3.2) 4(-24.13,-3.2) 5(-21.59,3.2) 6(-21.59,-3.2) 7(-19.05,3.2) 8(-19.05,-3.2) 9(-16.51,3.2) 10(-16.51,-3.2) 11(-13.97,3.2) 12(-13.97,-3.2) 13(-11.43,3.2) 14(-11.43,-3.2) 15(-8.89,3.2) 16(-8.89,-3.2) 17(-6.35,3.2) 18(-6.35,-3.2) 19(-3.81,3.2) 20(-3.81,-3.2) 21(-1.27,3.2) 22(-1.27,-3.2) 23(1.27,3.2) 24(1.27,-3.2) 25(3.81,3.2) 26(3.81,-3.2) 27(6.35,3.2) 28(6.35,-3.2) 29(8.89,3.2) 30(8.89,-3.2) 31(11.43,3.2) 32(11.43,-3.2) 33(13.97,3.2) 34(13.97,-3.2) 35(16.51,3.2) 36(16.51,-3.2) 37(19.05,3.2) 38(19.05,-3.2) 39(21.59,3.2) 40(21.59,-3.2) 41(24.13,3.2) 42(24.13,-3.2) 43(26.67,3.2) 44(26.67,-3.2)
  silkscreen extent -28.5,3.3 -28.1,3.7, body extent -27.94,-3.29 27.94,3.29, height 3.51
INDC1608X09N [mm] "Chip Inductor, 2-Leads, Body 1.60x0.80mm, IPC Medium Density"
  rect 0.87x0.98 smd: 1(-0.665,0) 2(0.665,0)
  body extent -0.87,-0.48 0.87,0.48, height 0.95
LED-KPT1608G-MFG [mm] "Kingbright Green KPT1608 LED in 1608 (0603) package"
  rect 0.8x0.8 smd: 1(-0.825,0)
  rect 0.8x0.8 smd mask+0.102: 2(0.825,0)
  body extent -0.81,-0.4 0.81,0.4, height 0.6
LED-KPT1608R-MFG [mm] "Kingbright Red KPT1608 LED in 1608 (0603) package"
  rect 0.8x0.8 smd: 1(-0.825,0)
  rect 0.8x0.8 smd mask+0.102: 2(0.825,0)
  silkscreen extent -0.12,-0.35 0.12,0.35, body extent -0.81,-0.4 0.81,0.4, height 0.6
MTG3,2_6,4-VIA [mm] "3,2mm ID/6.4mm OD mounting hole, reinforced with vias"
  round 1 hole 0.6: 1(-2.4,0) 1(-1.697,-1.697) 1(-1.697,1.697) 1(0,-2.4) 1(0,2.4) 1(1.697,-1.697) 1(1.697,1.697) 1(2.4,0)
  round 6.4 hole 3.2 paste-3.3: 1(0,0)
OSC500X320X85N [mm] "OSC, 4-Leads, Body 5.00x3.20mm, IPC Medium Density, Abracon"
  rect 1.2x1.1 smd: 1(-1.27,-1.15) 2(1.27,-1.15) 3(1.27,1.15) 4(-1.27,1.15)
  silkscreen extent -2.6,-2.15 2.6,1.6, body extent -2.5,-1.6 2.5,1.6, height 0.87
RESC1005N [mm] "Chip resistor C1005 (0402)."
  rrect51% 0.55x0.58 smd: 1(-0.475,0) 2(0.475,0)
  body extent -0.5,-0.25 0.5,0.25, height 0.33
RESC1608N [mm] "Chip resistor C1608 (0603)."
  rect 0.6x1 smd: 1(-0.7,0) 2(0.7,0)
  silkscreen extent 0,-0.5 0,0.5, body extent -0.8,-0.4 0.8,0.4, height 0.45
SAMTEC_TSW-103-07-G-S [mm] "Through-hole  .025\" SQ Post Header"
  rrect50% 1.4x1.4 hole 0.9: 1(0,2.54)
  round 1.4 hole 0.9: 2(0,0) 3(0,-2.54)
  silkscreen extent -1.27,-3.81 1.27,3.81, body extent -1.3,-3.87 1.24,3.87, height 8.38
SAMTEC_TSW-104-07-G-S [mm] "Pinheader male, square pin, 2.54 pitch, 1x4"
  rect 1.5x1.5 hole 0.9: 1(-3.81,0)
  round 1.5 hole 0.9: 2(-1.27,0) 3(1.27,0) 4(3.81,0)
  silkscreen extent -6.13,-1.26 5.08,1.26, body extent -5.31,-1.27 4.98,1.27, height 8.38
SAMTEC_TSW-105-07-G-S [mm] "Pinheader male, square pin, 2.54 pitch, height 2.5+6.1"
  rect 1.5x1.5 hole 0.9: 1(-5.08,0)
  round 1.5 hole 0.9: 2(-2.54,0) 3(0,0) 4(2.54,0) 5(5.08,0)
  silkscreen extent -6.6,-1.26 6.6,1.26, body extent -6.45,-1.27 6.37,1.27, height 8.38
SAMTEC_TSW-108-07-G-D [mm] "Through-Hole .025\" SQ Post Header, Vertical,  8x2 Position"
  rect 1.5x1.5 hole 0.9: 1(-8.89,-1.27)
  round 1.5 hole 0.9: 2(-8.89,1.27) 3(-6.35,-1.27) 4(-6.35,1.27) 5(-3.81,-1.27) 6(-3.81,1.27) 7(-1.27,-1.27) 8(-1.27,1.27) 9(1.27,-1.27) 10(1.27,1.27) 11(3.81,-1.27) 12(3.81,1.27) 13(6.35,-1.27) 14(6.35,1.27) 15(8.89,-1.27) 16(8.89,1.27)
  silkscreen extent -10.97,-2.5 10.16,2.5, body extent -10.16,-2.54 10.16,2.54, height 8.38
SAMTEC_TSW-110-07-G-D [mm] "Through-Hole .025\" SQ Post Header, Vertical,  10x2 Position"
  rect 1.5x1.5 hole 0.9: 1(-11.43,-1.27)
  round 1.5 hole 0.9: 2(-11.43,1.27) 3(-8.89,-1.27) 4(-8.89,1.27) 5(-6.35,-1.27) 6(-6.35,1.27) 7(-3.81,-1.27) 8(-3.81,1.27) 9(-1.27,-1.27) 10(-1.27,1.27) 11(1.27,-1.27) 12(1.27,1.27) 13(3.81,-1.27) 14(3.81,1.27) 15(6.35,-1.27) 16(6.35,1.27) 17(8.89,-1.27) 18(8.89,1.27) 19(11.43,-1.27) 20(11.43,1.27)
  silkscreen extent -13.57,-2.5 12.7,2.5, body extent -12.7,-2.54 12.7,2.54, height 8.38
SODFL250130X73N [mm] "SODFL, uSMP (DO-219AD), 2-Leads, Body 1.30x2.50mm, IPC Medium Density"
  rect 1.7x1.1 smd: 1(-0.8,0)
  rect 1x0.8 smd: 2(1.15,0)
  silkscreen extent -2.22,-0.8 1.15,0.8, body extent -1.25,-0.65 1.25,0.65, height 0.66
SOIC127P600X175-8N [mm] "SOIC, 8-Leads, Body 4.90x3.85mm, Pitch 1.27mm, IPC Medium Density"
  rect 1.45x0.6 smd: 1(-2.725,1.905)
  oval 1.45x0.6 smd: 2(-2.725,0.635) 3(-2.725,-0.635) 4(-2.725,-1.905) 5(2.725,-1.905) 6(2.725,-0.635) 7(2.725,0.635) 8(2.725,1.905)
  silkscreen extent -2.83,-2.5 1.6,2.7, body extent -3,-2.5 3,2.5, height 1.75
SON50P260X55_HS-11N-LF [mm] "SON, 10-Leads, Body 2.60x2.60mm, Pitch 0.50mm, Thermal Pad 2.15x1.19mm, IPC Medium Density"
  rect 0.85x0.25 smd: 1(-1.22,1) 2(-1.22,0.5) 3(-1.22,0) 4(-1.22,-0.5) 5(-1.22,-1) 6(1.22,-1) 7(1.22,-0.5) 8(1.22,0) 9(1.22,0.5) 10(1.22,1)
  rect 1.19x2.15 smd: 11(0,0)
  silkscreen extent -1.8,-1.5 1.35,1.55, body extent -1.35,-1.35 1.35,1.35, height 0.55
SOT95P280X130-3N [mm] "SOT23, 3-Leads, Body 2.95x2.80mm, Pitch 0.95mm, IPC Medium Density"
  rrect50% 0.9x0.6 smd: 1(-1.15,0.95) 2(-1.15,-0.95) 3(1.15,0)
  silkscreen extent -1.6,-1.5 0.7,1.6, body extent -1.3,-1.5 1.3,1.5, height 1.1
SOT230P700X180-4N-TI [mm] "SOT223, 4-Leads, Body 6.50x7.00mm (avg), Pitch 2.30mm, IPC Medium Density"
  rect 2.15x0.9 smd: 1(-2.925,2.3) 2(-2.925,0) 3(-2.925,-2.3)
  rect 2.15x3.2 smd: 4(2.925,0)
  silkscreen extent -3.05,-3.35 1.55,3.43, body extent -3.5,-3.35 3.5,3.35, height 1.8
TP100P254 [mm] "1mm testpoint for 2.54mm pitch"
  round 1.6 smd paste-1: 1(0,0)
  silkscreen extent -1.11,-1.11 1.11,1.11
TSQFP50P900X900X160-48N [mm] "TSQFP, 48-Leads, Body 7.00x7.00mm, Pitch 0.50mm, IPC Medium Density"
  oval 1.45x0.3 smd mask+0.05: 1(-4.225,2.75) 2(-4.225,2.25) 3(-4.225,1.75) 4(-4.225,1.25) 5(-4.225,0.75) 6(-4.225,0.25) 7(-4.225,-0.25) 8(-4.225,-0.75) 9(-4.225,-1.25) 10(-4.225,-1.75) 11(-4.225,-2.25) 12(-4.225,-2.75) 25(4.225,-2.75) 26(4.225,-2.25) 27(4.225,-1.75) 28(4.225,-1.25) 29(4.225,-0.75) 30(4.225,-0.25) 31(4.225,0.25) 32(4.225,0.75) 33(4.225,1.25) 34(4.225,1.75) 35(4.225,2.25) 36(4.225,2.75)
  oval 0.3x1.45 smd mask+0.05: 13(-2.75,-4.225) 14(-2.25,-4.225) 15(-1.75,-4.225) 16(-1.25,-4.225) 17(-0.75,-4.225) 18(-0.25,-4.225) 19(0.25,-4.225) 20(0.75,-4.225) 21(1.25,-4.225) 22(1.75,-4.225) 23(2.25,-4.225) 24(2.75,-4.225) 37(2.75,4.225) 38(2.25,4.225) 39(1.75,4.225) 40(1.25,4.225) 41(0.75,4.225) 42(0.25,4.225) 43(-0.25,4.225) 44(-0.75,4.225) 45(-1.25,4.225) 46(-1.75,4.225) 47(-2.25,4.225) 48(-2.75,4.225)
  silkscreen extent -4.35,-3.1 3.1,3.57, body extent -4.5,-4.5 4.5,4.5, height 1.6
VISHAY_T93YA [mm] "3/8\" Square Multi-Turn Cermet Trimmer"
  round 1.2 hole 0.7: 1(0,2.54) 2(0,0) 3(0,-2.54)
  silkscreen extent -2.3,-4.85 2.3,4.85, body extent -2.4,-4.76 2.4,4.77, height 11.55
WE-744042680 [mm] "Wuerth WE-TPC SMD Shielded Tiny Power Inductor, 2-Leads, Body 4.80x4.80mm, IPC Medium Density"
  rect 0.4x0.4 smd: 1(-2.5,0) 2(2.5,0)
  Top Layer region: 2.75,2.65 0.75,2.65 0.75,1.8 0.75,1.8 1.484,1.265 1.896,0.454 1.896,-0.454 1.484,-1.264 0.75,-1.8 0.75,-1.8 0.75,-1.8 0.75,-2.65 2.75,-2.65
  Top Layer region: -2.75,-2.65 -0.75,-2.65 -0.75,-1.8 -0.75,-1.8 -1.484,-1.265 -1.896,-0.454 -1.896,0.454 -1.484,1.264 -0.75,1.8 -0.75,1.8 -0.75,1.8 -0.75,2.65 -2.75,2.65
  silkscreen extent -0.3,-2.4 0.3,2.4, body extent -2.4,-2.4 2.4,2.4, height 1.82
WUERTH_7499021125 [mm] "Dual LAN-Transformer WE-RJ45LAN 10/100BaseT, body 31.4x21.5mm"
  round 1.4 hole 0.9: A1(-11.43,6.5) A2(-10.16,9.04) A3(-8.89,6.5) A4(-7.62,9.04) A5(-6.35,6.5) A6(-5.08,9.04) A7(-3.81,6.5) A8(-2.54,9.04) B1(2.54,6.5) B2(3.81,9.04) B3(5.08,6.5) B4(6.35,9.04) B5(7.62,6.5) B6(8.89,9.04) B7(10.16,6.5) B8(11.43,9.04)
  round 1.52 hole 1: A9(-13.47,-3.91) A10(-10.93,-3.91) A11(-3.05,-3.91) A12(-0.51,-3.91) B9(0.51,-2.14) B10(3.05,-2.14) B11(10.93,-3.91) B12(13.47,-3.91)
  round 2.4 hole 1.6: Shield(-15.465,3.2) Shield(0,10.44) Shield(15.465,3.2)
  round 3.25 hole 3.25 unplated: ""(-12.7,0.15) ""(12.7,0.15)
  silkscreen extent -16.86,-10.75 16.86,10.75, body extent -16.92,-10.75 16.92,10.75, height 14.81

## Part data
C1 C15: library part 50571, "Polarized capacitor, pin1 pos", Manufacturer=Nichicon, Part Number=UWT1V470MCL1GS
C2: library part 20078, "Ceramic chip capacitor", Manufacturer=Any, Package="1206 (3216 metric) chip capacitor", Part Number="4.7u, 50V, X5R, 1206 (3216 metric) chip capacitor", Voltage=50V
C3 C8 C9 C10 C11 C34 C36 C43 C45: library part 20111, "Ceramic chip capacitor", Manufacturer=Any, Package="0603 (1608 metric) chip capacitor", Part Number="10u, 10V, X5R, 0603 (1608 metric) chip capacitor", Voltage=10V
C4 C5 C6 C7 C14 C28 C31 C32 C35 C37 C40 C41 C44 C46: library part 20027, "Ceramic chip capacitor", Manufacturer=Any, Package="0603 (1608 metric) chip capacitor", Part Number="100n, 50V, X5R, 0603 (1608 metric) chip capacitor", Voltage=50V
C12 C13 C16 C17 C18 C19 C20 C21 C22 C23 C24 C25 C26 C27 C30: library part 20000, "Ceramic chip capacitor", Manufacturer=Any, Package="0402 (1005 metric) chip capacitor", Part Number="100n, 16V, X5R, 0402 (1005 metric) chip capacitor", Voltage=16V
C29 C33 C38 C39 C42 C47 C48: library part 20038, "Ceramic chip capacitor", Manufacturer=Any, Package="0603 (1608 metric) chip capacitor", Part Number="10n, 50V, X5R, 0603 (1608 metric) chip capacitor", Voltage=50V
D1: library part 50555, "TVS, Pin1 Cathode", Manufacturer=ST, Part Number=SMBJ33A
D2 D3: library part 50568, "Schottky Diode, pin1 cathode", Manufacturer=Vishay, Part Number=MSS1P6
D4 D6 D7: library part 50005, "LED, pin 1 cathode", Manufacturer=Kingbright, Part Number=KPT-1608SGC
D5: library part 50002, "LED, pin 1 cathode", Manufacturer=Kingbright, Part Number=KPT-1608EC
D8 D9: library part 50693, "TVS Diode Array", Manufacturer=Littelfuse, Part Number=SP3304NUTG
J1: library part 50537, "1X2 pin connector", Manufacturer="Metz Connect", Part Number=AKL320-02
J2 J3: library part 50289, "Trinamic 44-pin connector", Manufacturer=Samtec, Part Number=HLE-122-02-F-DV
J4: library part 50576, "2x8 pin connector", Manufacturer=Samtec, Part Number=TSW-108-07-G-D
J5: library part 50583, "2x10 pin connector", Manufacturer=Samtec, Part Number=TSW-110-07-G-D
J6 J7: library part 50584, "1X5 pin connector", Manufacturer=Samtec, Part Number=TSW-105-07-G-S
J8: library part 50585, "1X4 pin connector", Manufacturer=Samtec, Part Number=TSW-104-07-G-S
J9: library part 50579, "Dual LAN-Transformer WE-RJ45LAN 10/100BaseT", Manufacturer=Wuerth, Part Number=7499021125
JP1 JP2 JP3 JP4 JP5: library part 50570, "Jumper pin header", Manufacturer=Samtec, Part Number=TSW-103-07-G-S
L1 L4 L5 L6: library part 60036, "Ferrite bead", Current=1A, Manufacturer=Wuerth, Part Number=742792651, Tolerance=25
L2 L3: library part 60034, "Molded inductor", Current=0.5A, Manufacturer=Wuerth, Part Number=744042680, Tolerance=30
MP1 MP2 MP3 MP4: library part 50193, "Mounting hole", Part Number="M3 mounting hole"
Q1 Q2 Q3: library part 50574, "NPN BJT in 3-pin package, 1B 2E 3C", Manufacturer="Diodes Inc", Part Number=BC848A
R1 R2 R3 R4 R5 R6 R7 R8 R9 R10 R11 R12 R13 R14 R15 R16 R17 R18 R19 R20 R21: library part 10052, "Chip Resistor", Manufacturer=Any, Package="0402 (1005 metric) chip resistor", Part Number="0, -, -, 0402 (1005 metric) chip resistor", Power=-
R22: library part 10031, "Chip Resistor", Manufacturer=Any, Package="0603 (1608 metric) chip resistor", Part Number="1, 1%, 100mW, 0603 (1608 metric) chip resistor", Power=100mW, Tolerance=1%
R23: library part 50569, "Trimmer potentiometer", Manufacturer=Vishay, Part Number=T93YA104KT20
R24 R44 R49 R50 R56 R60 R61 R67: library part 10032, "Chip Resistor", Manufacturer=Any, Package="0603 (1608 metric) chip resistor", Part Number="4.7k, 1%, 100mW, 0603 (1608 metric) chip resistor", Power=100mW, Tolerance=1%
R25: library part 10164, "Chip Resistor", Manufacturer=Any, Package="0603 (1608 metric) chip resistor", Part Number="47k5, 1%, 100mW, 0603 (1608 metric) chip resistor", Power=100mW, Tolerance=1%
R26: library part 10050, "Chip Resistor", Manufacturer=Any, Package="0603 (1608 metric) chip resistor", Part Number="15k, 1%, 100mW, 0603 (1608 metric) chip resistor", Power=100mW, Tolerance=1%
R27: library part 10170, "Chip Resistor", Manufacturer=Any, Package="0603 (1608 metric) chip resistor", Part Number="33, 1%, 100mW, 0603 (1608 metric) chip resistor", Power=100mW, Tolerance=1%
R28 R30 R31 R32 R33 R35 R47: library part 10028, "Chip Resistor", Manufacturer=Any, Package="0603 (1608 metric) chip resistor", Part Number="10k, 1%, 100mW, 0603 (1608 metric) chip resistor", Power=100mW, Tolerance=1%
R29 R40 R41: library part 40007, "Chip Resistor", Manufacturer=DNP, Package="0603 (1608 metric) chip resistor"
R34 R48 R59: library part 10034, "Chip Resistor", Manufacturer=Any, Package="0603 (1608 metric) chip resistor", Part Number="22, 1%, 100mW, 0603 (1608 metric) chip resistor", Power=100mW, Tolerance=1%
R36 R37 R38 R39: library part 10049, "Chip Resistor", Manufacturer=Any, Package="0603 (1608 metric) chip resistor", Part Number="1k, 1%, 100mW, 0603 (1608 metric) chip resistor", Power=100mW, Tolerance=1%
R42 R43: library part 10054, "Chip Resistor", Manufacturer=Any, Package="0603 (1608 metric) chip resistor", Part Number="0, -, -, 0603 (1608 metric) chip resistor", Power=-
R45 R46: library part 10165, "Chip Resistor", Manufacturer=Any, Package="0603 (1608 metric) chip resistor", Part Number="2k, 1%, 100mW, 0603 (1608 metric) chip resistor", Power=100mW, Tolerance=1%
R51 R62: library part 10168, "Chip Resistor", Manufacturer=Any, Package="0603 (1608 metric) chip resistor", Part Number="6.19k, 1%, 100mW, 0603 (1608 metric) chip resistor", Power=100mW, Tolerance=1%
R52 R53 R54 R55 R63 R64 R65 R66: library part 10167, "Chip Resistor", Manufacturer=Any, Package="0603 (1608 metric) chip resistor", Part Number="5.1k, 1%, 100mW, 0603 (1608 metric) chip resistor", Power=100mW, Tolerance=1%
R57 R58 R68 R69: library part 10166, "Chip Resistor", Manufacturer=Any, Package="0603 (1608 metric) chip resistor", Part Number="510, 1%, 100mW, 0603 (1608 metric) chip resistor", Power=100mW, Tolerance=1%
S1: library part 50573, "Switch, 4 pin", Manufacturer=C&K, Part Number=KMR241NG
TP1 TP2 TP3 TP4 TP5 TP6 TP7 TP8 TP9 TP10 TP11: library part 50094, "Round testpoint"
U1: library part 50548, "LDO in SOT223 package", Manufacturer="Texas Instruments", Part Number=LM7805MP/NOPB
U2: library part 50499, "SPI Serial Flash Memory", Manufacturer=Atmel, Part Number=AT25128B-SSHL
U3: "Integrated EtherCAT Slave Controller", Manufacturer=Trinamic, Part Number=TMC8461-BA
U4: library part 50577, "I2C serial EEPROM in 8 pin case", Manufacturer=Microchip, Part Number=24LC64-/SN
U5 U6: library part 50580, "Single Port 10/100 MII/RMII/TP/Fiber  Fast Ethernet Transceiver", Manufacturer=ICplus
Y1: library part 50639, "Standard Clock Oscillators 100MHz 3.3Volts 25ppm -40C +85C 15pF", Manufacturer=Abracon, Part Number=ASFLMB-100.000MHZ-LR

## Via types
v1: diameter 0.5, hole 0.25, Top Layer to Bottom Layer, tented both sides, 379 vias
v2: diameter 0.5/0.5/0.5/0.5 (per signal layer), hole 0.25, Top Layer to Bottom Layer, tented both sides, 1 vias
v3: diameter 0.55, hole 0.25, Top Layer to Bottom Layer, tented both sides, 1 vias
